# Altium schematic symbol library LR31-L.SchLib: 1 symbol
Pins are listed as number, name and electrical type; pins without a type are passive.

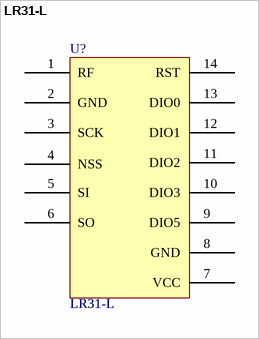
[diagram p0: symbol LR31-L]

## LR31-L
designator U?
footprint LR30
pins: 1 RF, 2 GND, 3 SCK, 4 NSS, 5 SI, 6 SO, 7 VCC, 8 GND, 9 DIO5, 10 DIO3, 11 DIO2, 12 DIO1, 13 DIO0, 14 RST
